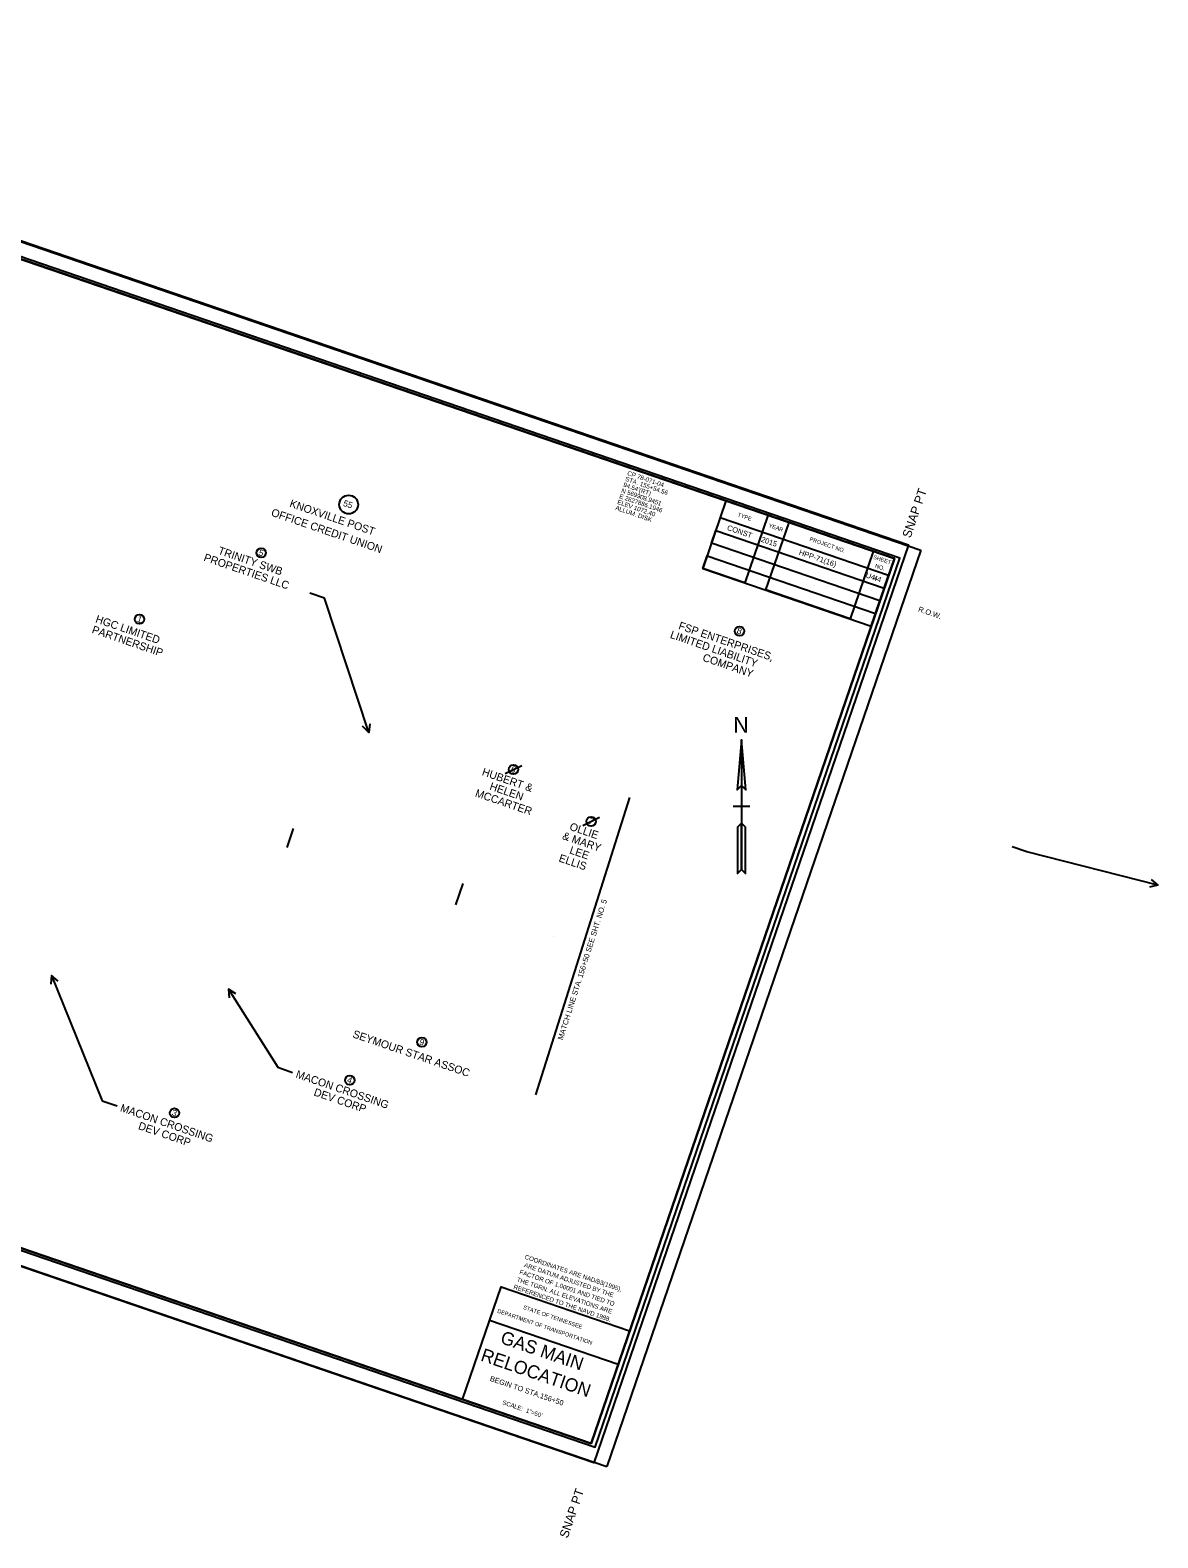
# Model space of a CAD drawing. Extents: x 2626331 to 2628652, y 569305 to 571035.
# Drawn here: x 2627386 to 2628652, y 569305 to 570998 of the extents above; entities that cross this region are included whole.
import ezdxf

# ---------------------------------------------------------------- set-up
doc = ezdxf.new("R2010")
doc.units = 0
for name, color, linetype in [('DESIGN - CENTERLINE - Proposed Text', 7, 'Continuous'), ('DESIGN - ROW - Wetland Mitigation Patterning', 7, 'Continuous'), ('DESIGN - SCRATCH - User 1', 7, 'Continuous'), ('DESIGN - SHEET - Corner Text', 7, 'Continuous'), ('DESIGN - SHEET - Light Grid', 7, 'Continuous'), ('DESIGN - SHEET - Linework', 7, 'Continuous'), ('DESIGN - SHEET - Plot Shape', 7, 'Continuous'), ('DESIGN - UTILITIES - Gas with Text', 7, 'Continuous'), ('SURVEY - CONTROL with Text', 7, 'Continuous'), ('SURVEY - PROPERTY - Owners', 7, 'Continuous'), ('SURVEY - PROPERTY - Tract Numbers', 7, 'Continuous')]:
    doc.layers.add(name, color=color, linetype=linetype)

msp = doc.modelspace()

# ---------------------------------------------------------------- linework, layer by layer
at = {"layer": 'DESIGN - CENTERLINE - Proposed Text'}
msp.add_lwpolyline([(2627953.5, 569802.8), (2628006.4, 569969.6), (2628059.3, 570136.4)], dxfattribs=at)
at = {"layer": 'DESIGN - SCRATCH - User 1'}
for p, q in [((2628181.7, 570435.4), (2628181.7, 570435.4)), ((2628176.8, 570421.2), (2628176.8, 570421.2)), ((2628216.7, 570423.4), (2628216.7, 570423.4)), ((2628172, 570407), (2628172, 570407)), ((2628207, 570395), (2628207, 570395)), ((2628211.8, 570409.2), (2628211.8, 570409.2)), ((2628275.8, 570403.1), (2628275.8, 570403.1)), ((2628167.1, 570392.8), (2628167.1, 570392.8)), ((2628202.1, 570380.8), (2628202.1, 570380.8)), ((2628270.9, 570388.9), (2628270.9, 570388.9)), ((2628334.9, 570382.9), (2628334.9, 570382.9)), ((2628266.1, 570374.8), (2628266.1, 570374.8)), ((2628330.1, 570368.7), (2628330.1, 570368.7)), ((2628261.2, 570360.6), (2628261.2, 570360.6)), ((2628325.2, 570354.5), (2628325.2, 570354.5)), ((2628320.3, 570340.3), (2628320.3, 570340.3)), ((2627973.8, 569980.7), (2627973.8, 569980.7)), ((2627958.7, 569480.4), (2627958.7, 569480.4))]:
    msp.add_line(p, q, dxfattribs=at)
at = {"layer": 'DESIGN - SHEET - Light Grid'}
msp.add_lwpolyline([(2626445.3, 569947.1), (2628020.3, 569407.2), (2628362.4, 570405.2), (2626787.4, 570945.1)], close=True, dxfattribs=at)
at = {"layer": 'DESIGN - SHEET - Linework'}
for p, q in [((2626683.1, 570997.9), (2628385.9, 570414.3)), ((2628385.9, 570414.3), (2628033.2, 569385.6)), ((2628184.4, 570126.4), (2628175, 570126.4)), ((2628193.9, 570126.4), (2628184.4, 570126.4)), ((2626330.5, 569969.3), (2628033.2, 569385.6))]:
    msp.add_line(p, q, dxfattribs=at)
for points in [[(2626867, 570915.1), (2626526.5, 569921.9), (2628015.7, 569411.4), (2628356.1, 570404.7), (2626867, 570915.1)], [(2628166.9, 570469.5), (2628141, 570393.8), (2628330.2, 570329), (2628356.1, 570404.7), (2628332.5, 570412.8), (2628306.5, 570337.1), (2628212, 570369.5), (2628237.9, 570445.2), (2628214.2, 570453.3), (2628188.3, 570377.6), (2628141, 570393.8), (2628145.9, 570408), (2628335.1, 570343.2), (2628339.9, 570357.4), (2628150.7, 570422.2), (2628155.6, 570436.4), (2628344.8, 570371.6), (2628349.7, 570385.7), (2628160.5, 570450.6)], [(2628184.4, 570201.4), (2628179.5, 570145.1), (2628184.4, 570150), (2628189.3, 570145.1), (2628184.4, 570201.4), (2628184.4, 570055.9), (2628189, 570051.4), (2628189, 570103.1), (2628184.4, 570107.7), (2628179.9, 570103.1), (2628179.9, 570051.4), (2628184.4, 570055.9)], [(2627871.4, 569460.9), (2627914.7, 569587.3), (2628059, 569537.8), (2628046, 569500), (2627901.8, 569549.4)]]:
    msp.add_lwpolyline(points, dxfattribs=at)
for points in [[(2628184.4, 570150), (2628189.3, 570145.1), (2628184.4, 570201.4)], [(2628179.9, 570051.4), (2628184.4, 570055.9), (2628184.4, 570107.7), (2628179.9, 570103.1)]]:
    msp.add_lwpolyline(points, close=True, dxfattribs=at)
at = {"layer": 'DESIGN - SHEET - Plot Shape'}
for points in [[(2626763.7, 570971.4), (2628371.8, 570420.1), (2628018.6, 569389.6), (2626410.4, 569940.8)], [(2626786.5, 570942.7), (2628356.1, 570404.7), (2628015.7, 569411.4), (2626446.1, 569949.5)]]:
    msp.add_lwpolyline(points, close=True, dxfattribs=at)
at = {"layer": 'DESIGN - UTILITIES - Gas with Text'}
for p, q in [((2627674.4, 570080.4), (2627681.7, 570101.7)), ((2627863.8, 570016.1), (2627872, 570040.1))]:
    msp.add_line(p, q, dxfattribs=at)
at = {"layer": 'SURVEY - PROPERTY - Tract Numbers'}
for p, q in [((2627919.2, 570163.4), (2627938.1, 570172.6)), ((2628006.3, 570105.1), (2628025.1, 570114.4))]:
    msp.add_line(p, q, dxfattribs=at)
for points in [[(2627716.4, 570360.5), (2627699.9, 570366.1)], [(2627766.1, 570209.6), (2627716.4, 570360.5)], [(2627767.5, 570219.3), (2627766.1, 570209.6), (2627759.2, 570216.5)], [(2628504.8, 570075.4), (2628488.2, 570081.1)], [(2628651.8, 570038), (2628504.8, 570075.4)], [(2628644.4, 570044.4), (2628651.8, 570038), (2628642.3, 570035.9)], [(2627417.4, 569930.4), (2627410.1, 569936.9), (2627409.3, 569927.1)], [(2627410.1, 569936.9), (2627467, 569796)], [(2627608.6, 569921.3), (2627664, 569833.7)], [(2627617, 569916.3), (2627608.6, 569921.3), (2627609.6, 569911.6)], [(2627664, 569833.7), (2627680.5, 569828)], [(2627467, 569796), (2627483.6, 569790.3)]]:
    msp.add_lwpolyline(points, dxfattribs=at)
for centre, radius in [((2627743.6, 570465.4), 10.5), ((2627645.5, 570411.2), 5.25), ((2627508.7, 570336.6), 5.25), ((2628182.3, 570323.4), 5.25), ((2627928.6, 570168), 5.25), ((2628015.7, 570109.7), 5.25), ((2627825.8, 569861.9), 5.25), ((2627744.8, 569819.2), 5.25), ((2627548.1, 569782.4), 5.25)]:
    msp.add_circle(centre, radius, dxfattribs=at)

# ---------------------------------------------------------------- texts
at = {"layer": 'DESIGN - CENTERLINE - Proposed Text'}
msp.add_text('MATCH LINE STA. 156+50 SEE SHT. NO. 5', height=6, rotation=72.3958, dxfattribs=at).set_placement((2627983.8, 569863.8))
at = {"layer": 'DESIGN - ROW - Wetland Mitigation Patterning'}
msp.add_text('4', height=6, rotation=341.0785, dxfattribs=at).set_placement((2628331.9, 570380.7))
at = {"layer": 'DESIGN - SHEET - Corner Text'}
for s, height, rotation, p in [('  SNAP PT', 10, 71.0785, (2628371.8, 570420.1)), ('TYPE', 4.5, 341.0785, (2628179.7, 570452.2)), ('CONST', 6, 341.0785, (2628167.8, 570437)), ('2015', 6, 341.0785, (2628205.9, 570423.9)), ('YEAR', 4.5, 341.0785, (2628214.5, 570440.1)), ('PROJECT NO.', 4.5, 341.0785, (2628260.5, 570424.8)), ('HPP-71(16)', 6, 341.0785, (2628248.5, 570409.3)), ('SHEET', 4.5, 341.0785, (2628332, 570404.7)), ('NO.', 4.5, 341.0785, (2628334, 570394.8)), ('U4-4', 6, 341.0785, (2628323.4, 570383.8)), ('R.O.W.', 6, 341.0785, (2628382.3, 570345.5)), ('COORDINATES ARE NAD/83(1995),', 5, 341.0785, (2627940.8, 569618.9)), ('FACTOR OF 1.00001 AND TIED TO', 5, 341.0785, (2627934.8, 569601.9)), ('ARE DATUM ADJUSTED BY THE', 5, 341.0785, (2627940, 569609.7)), ('REFERENCED TO THE NAVD 1988.', 5, 341.0785, (2627928.1, 569585.2)), ('THE TGRN. ALL ELEVATIONS ARE', 5, 341.0785, (2627931.8, 569593.4)), ('STATE OF TENNESSEE', 4.5, 341.0785, (2627939, 569562.5)), ('DEPARTMENT OF TRANSPORTATION', 4.5, 341.0785, (2627910, 569558.4)), ('GAS MAIN ', 14.76, 341.0785, (2627912.8, 569524.4)), ('RELOCATION ', 14.764, 341.0785, (2627890.8, 569504.7)), ('BEGIN TO STA.156+50', 5.905, 341.0785, (2627901.6, 569481.9)), ('SCALE:  1"=50\'', 4.921, 341.0785, (2627915.6, 569455.5)), ('SNAP PT  ', 10, 71.0785, (2627989.4, 569304.4))]:
    msp.add_text(s, height=height, rotation=rotation, dxfattribs=at).set_placement(p)
at = {"layer": 'DESIGN - SHEET - Linework'}
msp.add_text('N', height=17.7, dxfattribs=at).set_placement((2628175.4, 570209.4))
at = {"layer": 'SURVEY - CONTROL with Text'}
for s, p in [('CP 78-071-04', (2628055.8, 570498.7)), ('N 569908.9451', (2628049.1, 570479.2)), ("94.54'(RT)", (2628051.3, 570485.7)), ('STA. 155+54.56', (2628053.6, 570492.2)), ('ALLUM. DISK', (2628042.4, 570459.7)), ('ELEV 1072.40', (2628044.7, 570466.2)), ('E 2627886.1946', (2628046.9, 570472.7))]:
    msp.add_text(s, height=5, rotation=341.0785, dxfattribs=at).set_placement(p)
at = {"layer": 'SURVEY - PROPERTY - Owners'}
for s, p in [('KNOXVILLE POST ', (2627676.6, 570463.1)), ('OFFICE CREDIT UNION', (2627655.9, 570453)), ('TRINITY SWB', (2627596.3, 570410.2)), ('PROPERTIES LLC', (2627580.2, 570402.5)), ('PARTNERSHIP', (2627454.7, 570321.5)), ('HGC LIMITED', (2627458.7, 570333.3)), ('FSP ENTERPRISES,', (2628113.1, 570325.9)), ('LIMITED LIABILITY', (2628103.7, 570315.9)), ('COMPANY', (2628140.1, 570290.2)), ('HUBERT &', (2627892.5, 570161.8)), ('MCCARTER', (2627884.9, 570138)), ('HELEN', (2627901.1, 570145.6)), ('OLLIE', (2627990.8, 570100.4)), ('& MARY', (2627982.7, 570090)), ('LEE', (2627990.8, 570074)), ('ELLIS', (2627978.7, 570065)), ('SEYMOUR STAR ASSOC', (2627747.3, 569867.5)), ('MACON CROSSING', (2627683.5, 569822.4)), ('DEV CORP', (2627703.7, 569802.3)), ('MACON CROSSING', (2627486.5, 569784.6)), ('DEV CORP', (2627506.7, 569764.5))]:
    msp.add_text(s, height=8.75, rotation=341.0785, dxfattribs=at).set_placement(p)
at = {"layer": 'SURVEY - PROPERTY - Tract Numbers'}
for s, p in [('55', (2627736.8, 570464.1)), ('5', (2627641.9, 570408.7)), ('1', (2627505.4, 570334.1)), ('8', (2628178.6, 570321)), ('6', (2627924.9, 570165.6)), ('7', (2628012.1, 570107.3)), ('9', (2627822.2, 569859.5)), ('4', (2627741.2, 569816.8)), ('3', (2627544.5, 569779.9))]:
    msp.add_text(s, height=7, rotation=341.0785, dxfattribs=at).set_placement(p)

doc.saveas('drawing.dxf')
